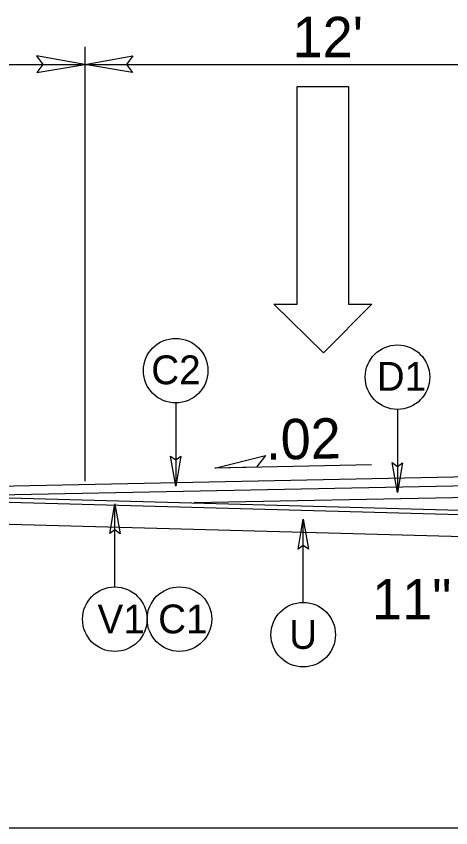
# Model space of a CAD drawing. Extents: x 957297 to 961629, y 830661 to 840840.
# Drawn here: x 959319.7 to 959403.5, y 837314.9 to 837471.6 of the extents above; entities that cross this region are included whole.
import ezdxf

# ---------------------------------------------------------------- set-up
doc = ezdxf.new("R2010")
doc.units = 0
for name, color, linetype in [('Old_Level_1', 7, 'Continuous'), ('Old_Level_11', 7, 'Continuous'), ('Prop CMT Pvmt Milling', 7, 'Continuous'), ('Prop Dimension Text', 7, 'Continuous'), ('Prop Lane Arrow CELL', 7, 'Continuous'), ('Typical ID Circle CELL', 7, 'Continuous'), ('Typical Terminator CELL', 7, 'Continuous'), ('Typical Text ID Circle CELL', 7, 'Continuous')]:
    doc.layers.add(name, color=color, linetype=linetype)

# ---------------------------------------------------------------- blocks, each defined once
blk = doc.blocks.new('Lane Arrow Through')
at = {"layer": 'Prop Lane Arrow CELL'}
for p, q in [((-3.15, 1.6), (-3.15, 3.1)), ((-3.15, 3.1), (0, 0)), ((-17.15, 1.6), (-3.15, 1.6)), ((-17.15, -1.7), (-17.15, 1.6)), ((0, 0), (-3.15, -3.2)), ((-3.15, -1.7), (-17.15, -1.7)), ((-3.15, -3.2), (-3.15, -1.7))]:
    blk.add_line(p, q, dxfattribs=at)

msp = doc.modelspace()

# ---------------------------------------------------------------- linework, layer by layer
at = {"layer": 'Old_Level_1'}
for p, q in [((959332.9, 837465.69), (959332.9, 837381.79)), ((959239.42, 837462.34), (959332.9, 837462.34)), ((959332.9, 837462.34), (959426.38, 837462.34)), ((959388.24, 837384.96), (959358.04, 837384.35)), ((959426.38, 837383.05), (959206.42, 837378.6)), ((959426.42, 837381.32), (959206.42, 837376.87)), ((959419.77, 837378.93), (959354.01, 837377.6)), ((959133.56, 837314.86), (959479.39, 837314.86))]:
    msp.add_line(p, q, dxfattribs=at)
msp.add_lwpolyline([(959306.49, 837373.85), (959479.42, 837369.14)], dxfattribs=at)
at = {"layer": 'Old_Level_11'}
for p, q in [((959358.04, 837384.35), (959367.79, 837386.77)), ((959367.79, 837386.77), (959366.06, 837384.51)), ((959366.06, 837384.51), (959358.04, 837384.35))]:
    msp.add_line(p, q, dxfattribs=at)
at = {"layer": 'Prop CMT Pvmt Milling'}
for points in [[(959306.49, 837378.9), (959426.46, 837375.63)], [(959426.44, 837374.75), (959306.51, 837378.02)]]:
    msp.add_lwpolyline(points, dxfattribs=at)
at = {"layer": 'Typical ID Circle CELL'}
for p, q in [((959350.46, 837396.95), (959350.46, 837380.86)), ((959393.26, 837395.69), (959393.26, 837379.6)), ((959338.71, 837361.38), (959338.71, 837377.46)), ((959375.07, 837358.38), (959375.07, 837374.47))]:
    msp.add_line(p, q, dxfattribs=at)
for centre in [(959350.46, 837403.17), (959393.26, 837401.91), (959338.71, 837355.15), (959351.19, 837355.17), (959375.07, 837352.16)]:
    msp.add_circle(centre, 6.23, dxfattribs=at)
at = {"layer": 'Typical Terminator CELL'}
for points in [[(959323.67, 837460.75), (959332.9, 837462.34), (959323.62, 837463.98), (959324.8, 837462.34)], [(959342.12, 837460.75), (959332.9, 837462.34), (959342.17, 837463.98), (959340.99, 837462.34)], [(959351.45, 837386.63), (959350.46, 837380.86), (959349.44, 837386.66), (959350.46, 837385.92)], [(959394.25, 837385.36), (959393.26, 837379.6), (959392.23, 837385.4), (959393.26, 837384.66)], [(959337.72, 837371.7), (959338.71, 837377.46), (959339.74, 837371.67), (959338.71, 837372.4)], [(959374.08, 837368.71), (959375.07, 837374.47), (959376.1, 837368.67), (959375.07, 837369.41)]]:
    msp.add_lwpolyline(points, close=True, dxfattribs=at)

# ---------------------------------------------------------------- block references
at = {"layer": 'Old_Level_1', "xscale": 3, "yscale": 3, "rotation": -90.00000000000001}
msp.add_blockref('Lane Arrow Through', (959378.99, 837406.58), dxfattribs=at)

# ---------------------------------------------------------------- texts
at = {"layer": 'Prop Dimension Text'}
for s, rotation, p in [("12'", 0, (959373.02, 837463.72)), ('.02', 1.1839, (959367.9, 837385.93)), ('11"', 0, (959388.35, 837355.1))]:
    msp.add_text(s, height=7.801, rotation=rotation, dxfattribs=at).set_placement(p)
at = {"layer": 'Typical Text ID Circle CELL'}
for s, height, p in [('C2', 5.572, (959345.75, 837400.54)), ('D1', 5.572, (959389.26, 837399.28)), ('V1', 5.572, (959335.37, 837352.41)), ('C1', 5.572, (959347.08, 837352.41)), ('U', 5.57, (959372.37, 837349.42))]:
    msp.add_text(s, height=height, dxfattribs=at).set_placement(p)

doc.saveas('drawing.dxf')
